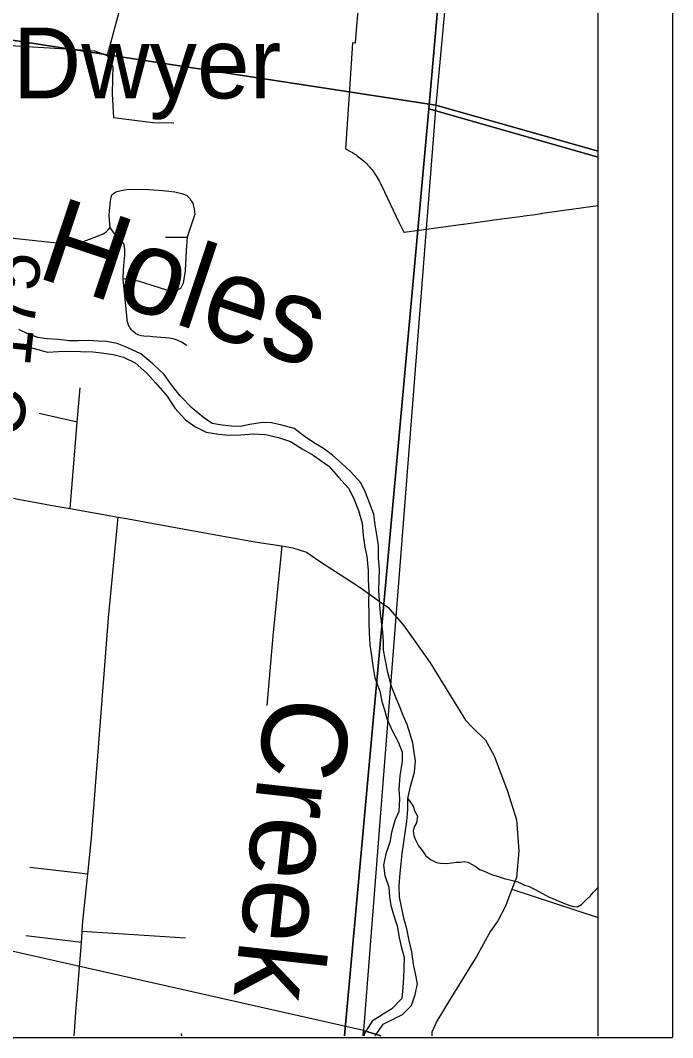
# Model space of a CAD drawing. Extents: x 0 to 34, y 0 to 22.
# Drawn here: x 8.273 to 9, y 14 to 15.134 of the extents above; entities that cross this region are included whole.
import ezdxf

# ---------------------------------------------------------------- set-up
doc = ezdxf.new("R2010")
doc.units = 0
for name, color, linetype in [('GM_X_County_Road', 7, 'Continuous'), ('GM_X_County_Road_Text', 7, 'Continuous'), ('GM_X_Interchange_Ramps', 7, 'Continuous'), ('GM_X_Interstate_Route', 7, 'Continuous'), ('GM_X_Minor_River', 7, 'Continuous'), ('GM_X_Minor_River_Text', 7, 'Continuous'), ('GM_X_Section', 7, 'Continuous'), ('GM_X_State_Shield', 7, 'Continuous'), ('GM_X_Township_Road', 7, 'Continuous'), ('GM_X_Unincorporated_Text', 7, 'Continuous'), ('SH_Data', 7, 'Continuous')]:
    doc.layers.add(name, color=color, linetype=linetype)

msp = doc.modelspace()

# ---------------------------------------------------------------- linework, layer by layer
at = {"layer": 'GM_X_County_Road'}
for points in [[(8.265, 14.6016), (8.2702, 14.6006), (8.3102, 14.5931), (8.328, 14.59), (8.3817, 14.5804), (8.3909, 14.5788)], [(8.3909, 14.5788), (8.4212, 14.5734), (8.4637, 14.5657)], [(8.4637, 14.5657), (8.5052, 14.5581), (8.5298, 14.5537), (8.5387, 14.5523), (8.5641, 14.5483), (8.5766, 14.5463), (8.5915, 14.5414), (8.6063, 14.5315), (8.6482, 14.5043), (8.6542, 14.5001)], [(8.6542, 14.5001), (8.678, 14.483), (8.6796, 14.4819)], [(8.6796, 14.4819), (8.6827, 14.4797), (8.7, 14.4599), (8.7296, 14.418), (8.7691, 14.3539), (8.7765, 14.3464), (8.7913, 14.3316), (8.8011, 14.3144), (8.8159, 14.2749), (8.8258, 14.2428), (8.8283, 14.2083), (8.8258, 14.1787), (8.8208, 14.1656), (8.8135, 14.1466), (8.8049, 14.1302), (8.797, 14.1187), (8.7811, 14.0904), (8.7518, 14.043), (8.737, 14.0183), (8.7315, 14.0062), (8.7313, 14.0019)]]:
    msp.add_lwpolyline(points, dxfattribs=at)
at = {"layer": 'GM_X_Interchange_Ramps'}
msp.add_lwpolyline([(8.6497, 15.1532), (8.6475, 15.1278), (8.646, 15.1095), (8.6459, 15.109), (8.643, 15.1092), (8.6396, 15.0577), (8.6352, 14.9911), (8.6383, 14.9895), (8.6399, 14.9887), (8.6415, 14.9878), (8.6428, 14.987), (8.6439, 14.9863), (8.6449, 14.9857), (8.6455, 14.9853), (8.6469, 14.9844), (8.6486, 14.9831), (8.6501, 14.982), (8.6517, 14.9808), (8.6531, 14.9796), (8.6548, 14.9781), (8.6566, 14.9765), (8.6585, 14.9747), (8.6598, 14.9734), (8.6607, 14.9723), (8.6611, 14.9719), (8.6622, 14.9707), (8.6632, 14.9695), (8.6645, 14.968), (8.6656, 14.9666), (8.667, 14.9645), (8.6684, 14.9626), (8.6695, 14.9609), (8.6706, 14.9591), (8.6717, 14.9573), (8.6726, 14.9555), (8.6734, 14.954), (8.6742, 14.9524), (8.6786, 14.9433), (8.6948, 14.9094), (8.7002, 14.8981), (8.7007, 14.8982), (8.728, 14.9019), (8.7659, 14.9071), (8.7665, 14.9072), (8.7672, 14.9072), (8.7694, 14.9075), (8.7989, 14.9116), (8.8004, 14.9118), (8.8329, 14.9162), (8.8344, 14.9164), (8.8465, 14.918), (8.8539, 14.9191), (8.8546, 14.9192), (8.9171, 14.9279), (8.9171, 17.2013)], dxfattribs=at)
at = {"layer": 'GM_X_Interstate_Route'}
for points in [[(8.745, 15.2262), (8.728, 15.0359), (8.9171, 14.9817), (8.9171, 17.2013)], [(8.634, 14.0019), (8.6778, 14.4836), (8.728, 15.0359), (8.745, 15.2262)], [(8.9171, 14.0019), (8.9171, 14.9817), (8.728, 15.0359), (8.6778, 14.4836), (8.634, 14.0019)]]:
    msp.add_lwpolyline(points, dxfattribs=at)
at = {"layer": 'GM_X_Minor_River'}
for points in [[(8.6683, 14.0019), (8.6771, 14.0152), (8.689, 14.021), (8.6989, 14.0258), (8.7086, 14.0359), (8.713, 14.0483), (8.7155, 14.0601), (8.7131, 14.0715), (8.711, 14.0818), (8.709, 14.0956), (8.7062, 14.1082), (8.7034, 14.1215), (8.7006, 14.1319), (8.6975, 14.146), (8.6954, 14.1567), (8.6949, 14.1692), (8.6963, 14.1833), (8.6973, 14.1943), (8.6983, 14.2053), (8.7, 14.2155), (8.7017, 14.2284), (8.7035, 14.241), (8.7045, 14.2546), (8.7048, 14.2668), (8.7077, 14.28), (8.7122, 14.2959), (8.7132, 14.3085), (8.7118, 14.318), (8.7101, 14.3283), (8.7073, 14.3386), (8.7041, 14.3493), (8.6994, 14.3593), (8.6958, 14.3689), (8.6918, 14.3785), (8.6863, 14.3915), (8.6825, 14.4072), (8.6794, 14.4225), (8.6776, 14.432), (8.6775, 14.4415), (8.6769, 14.4526), (8.6752, 14.4636), (8.6743, 14.4735), (8.673, 14.4876), (8.6725, 14.4987), (8.673, 14.5223), (8.6721, 14.5345), (8.672, 14.5485), (8.6703, 14.5585), (8.6682, 14.5718), (8.6666, 14.5836), (8.6619, 14.5963), (8.6576, 14.6078), (8.6521, 14.6185), (8.6409, 14.6313), (8.6309, 14.6402), (8.6208, 14.6496), (8.6107, 14.657), (8.6006, 14.6629), (8.5901, 14.67), (8.5778, 14.6793), (8.5642, 14.683), (8.5525, 14.6855), (8.5426, 14.6861), (8.5285, 14.6837), (8.5179, 14.6816), (8.508, 14.6818), (8.4978, 14.6828), (8.4864, 14.6849), (8.4767, 14.6915), (8.464, 14.7021), (8.4506, 14.7156), (8.441, 14.728), (8.4329, 14.7396), (8.4202, 14.7512), (8.4068, 14.7625), (8.3917, 14.7697), (8.3804, 14.7741), (8.3687, 14.7762), (8.3592, 14.7768), (8.3483, 14.7774), (8.3369, 14.7772), (8.327, 14.777), (8.3149, 14.7784), (8.3024, 14.7794), (8.2922, 14.7807), (8.2809, 14.7847), (8.2707, 14.7895)], [(8.2606, 14.7749), (8.2745, 14.7723), (8.2881, 14.7686), (8.3029, 14.7645), (8.315, 14.7651), (8.3275, 14.7656), (8.3397, 14.7653), (8.3533, 14.7647), (8.3632, 14.7637), (8.376, 14.7616), (8.3877, 14.7587), (8.4005, 14.7524), (8.4136, 14.7411), (8.4232, 14.7302), (8.4362, 14.7155), (8.445, 14.7021), (8.4569, 14.6889), (8.467, 14.6815), (8.4798, 14.6751), (8.4938, 14.673), (8.5048, 14.672), (8.5184, 14.6721), (8.5321, 14.6734), (8.5458, 14.6727), (8.5605, 14.6694), (8.5737, 14.6646), (8.5868, 14.6567), (8.5992, 14.6496), (8.6164, 14.6371), (8.6275, 14.6251), (8.6387, 14.6123), (8.6449, 14.6), (8.6496, 14.5878), (8.6539, 14.5736), (8.6547, 14.5599), (8.6567, 14.5469), (8.6588, 14.5366), (8.6604, 14.521), (8.6606, 14.5107), (8.6611, 14.4974), (8.6609, 14.486), (8.661, 14.473), (8.6612, 14.4631), (8.6617, 14.4513), (8.6622, 14.438), (8.6642, 14.4258), (8.6655, 14.4148), (8.6679, 14.4014), (8.6733, 14.3865), (8.6758, 14.375), (8.6786, 14.3654), (8.6811, 14.3559), (8.6869, 14.3432), (8.6939, 14.3298), (8.6982, 14.3183), (8.6984, 14.3084), (8.6958, 14.2921), (8.6947, 14.2769), (8.6953, 14.2662), (8.6946, 14.2522), (8.6902, 14.242), (8.6866, 14.2287), (8.6845, 14.2181), (8.68, 14.2049), (8.6775, 14.1924), (8.6792, 14.181), (8.6835, 14.1679), (8.6844, 14.1569), (8.6857, 14.1474), (8.6893, 14.1347), (8.6929, 14.1248), (8.6949, 14.1118), (8.6974, 14.1015), (8.7005, 14.0893), (8.7003, 14.0771), (8.6997, 14.0676), (8.6991, 14.0558), (8.6978, 14.0437), (8.6869, 14.0321), (8.6773, 14.0262), (8.665, 14.0184), (8.656, 14.0042), (8.656, 14.0019)], [(8.7048, 14.2668), (8.7111, 14.2574), (8.7118, 14.2537), (8.7155, 14.2471), (8.7145, 14.2395), (8.7117, 14.235), (8.7105, 14.2301), (8.7115, 14.2255), (8.7129, 14.2213), (8.7165, 14.214), (8.721, 14.2082), (8.7246, 14.2028), (8.7299, 14.1985), (8.7366, 14.1953), (8.7412, 14.1944), (8.7476, 14.1942), (8.7537, 14.1948), (8.7587, 14.1955), (8.7629, 14.1958), (8.7675, 14.1964), (8.7716, 14.1955), (8.7757, 14.1935), (8.7806, 14.1907), (8.7847, 14.1876), (8.7889, 14.186), (8.793, 14.184), (8.7979, 14.182), (8.8043, 14.1799), (8.8122, 14.1774), (8.8213, 14.1753), (8.8274, 14.1736), (8.8349, 14.17), (8.8394, 14.1688), (8.8465, 14.1652), (8.8623, 14.1568), (8.8665, 14.1552), (8.8732, 14.1523), (8.8777, 14.1503), (8.8853, 14.1475), (8.8894, 14.1462), (8.894, 14.1457), (8.8982, 14.1483), (8.9037, 14.1535), (8.908, 14.1579), (8.9115, 14.162), (8.9166, 14.1672), (8.9171, 14.1686)]]:
    msp.add_lwpolyline(points, dxfattribs=at)
at = {"layer": 'GM_X_Section'}
for points in [[(7.8045, 16.1663), (8.8322, 16.077), (8.7359, 15.0399), (7.7155, 15.1965)], [(7.7155, 15.1965), (8.7359, 15.0399), (8.6553, 14.0079), (7.6347, 14.2379)]]:
    msp.add_lwpolyline(points, close=True, dxfattribs=at)
at = {"layer": 'GM_X_State_Shield'}
msp.add_lwpolyline([(8.9171, 14.9885), (8.9171, 16.0539), (8.8322, 16.077), (8.7359, 15.0399)], close=True, dxfattribs=at)
for points in [[(8.9171, 14.0019), (8.9171, 14.9885), (8.7359, 15.0399), (8.6553, 14.0079), (8.6744, 14.0019)], [(8.6547, 14.0019), (8.6553, 14.0079), (7.6347, 14.2379), (7.6133, 14.0019)], [(8.6744, 14.0019), (8.6553, 14.0079), (8.6547, 14.0019)]]:
    msp.add_lwpolyline(points, dxfattribs=at)
at = {"layer": 'GM_X_Township_Road'}
for p, q in [((8.4345, 14.8927), (8.4586, 14.8927)), ((8.336, 14.6863), (8.2936, 14.696)), ((8.3478, 14.1822), (8.2832, 14.1898)), ((8.8208, 14.1656), (8.9171, 14.1338)), ((8.3406, 14.1061), (8.2787, 14.1135)), ((8.3416, 14.1187), (8.4569, 14.1113)), ((8.4526, 14.0019), (8.4521, 14.0048))]:
    msp.add_line(p, q, dxfattribs=at)
for points in [[(8.3834, 15.1477), (8.3695, 15.0951)], [(8.1826, 15.0878), (8.219, 15.0927), (8.2438, 15.1034), (8.2554, 15.1068), (8.336, 15.1019), (8.3554, 15.1005), (8.3695, 15.0951), (8.3758, 15.083), (8.3753, 15.0694), (8.3748, 15.0524), (8.3763, 15.0262), (8.4204, 15.0204), (8.4438, 15.0203)], [(8.4583, 14.7717), (8.4523, 14.7757), (8.4473, 14.7779), (8.4431, 14.7792), (8.4385, 14.78), (8.434, 14.7802), (8.42, 14.7816), (8.415, 14.7821), (8.4125, 14.782), (8.4102, 14.7821), (8.4078, 14.7825), (8.4045, 14.7835), (8.401, 14.7853), (8.398, 14.7877), (8.3966, 14.7893), (8.3957, 14.7903), (8.3945, 14.792), (8.3932, 14.7945), (8.3923, 14.797), (8.3918, 14.7992), (8.3918, 14.8012), (8.3872, 14.8461), (8.3874, 14.8563), (8.3884, 14.8653), (8.3889, 14.8726), (8.3889, 14.8791), (8.3878, 14.8855), (8.3854, 14.8885), (8.3776, 14.8964), (8.3728, 14.9034), (8.3719, 14.9118), (8.3717, 14.9166), (8.3719, 14.9219), (8.373, 14.9328), (8.3737, 14.9374), (8.3747, 14.9399), (8.3766, 14.9415), (8.3792, 14.9432), (8.385, 14.9448), (8.3912, 14.9459), (8.3948, 14.9463), (8.4158, 14.9456), (8.4315, 14.9447), (8.445, 14.9431), (8.4537, 14.9411), (8.4583, 14.939), (8.4602, 14.9372), (8.4615, 14.9356), (8.4632, 14.933), (8.4649, 14.9304), (8.4653, 14.9287), (8.4663, 14.9241), (8.467, 14.9182), (8.4586, 14.8927), (8.4576, 14.8777), (8.4564, 14.8551), (8.4542, 14.8413), (8.451, 14.8352), (8.4431, 14.8314), (8.4042, 14.8437), (8.3872, 14.8461)], [(8.1992, 14.8986), (8.327, 14.8849), (8.3293, 14.8849), (8.3314, 14.885), (8.3342, 14.8852), (8.345, 14.8887), (8.3624, 14.8951), (8.3649, 14.8965), (8.3682, 14.8987), (8.3705, 14.9009), (8.3728, 14.9034)], [(8.328, 14.59), (8.336, 14.6863), (8.3391, 14.7248)], [(8.3325, 14.0019), (8.3348, 14.033), (8.3406, 14.1061), (8.3416, 14.1187), (8.3424, 14.1298), (8.3478, 14.1822), (8.352, 14.2229), (8.3596, 14.3236), (8.371, 14.468), (8.3817, 14.5804)], [(8.5641, 14.5483), (8.5542, 14.4476), (8.5476, 14.3702)]]:
    msp.add_lwpolyline(points, dxfattribs=at)
at = {"layer": 'SH_Data'}
for p in [(9, 17.3211), (2, 14)]:
    msp.add_line(p, (9, 14), dxfattribs=at)

# ---------------------------------------------------------------- texts
at = {"layer": 'GM_X_County_Road_Text'}
msp.add_text('C-175', height=0.05682, rotation=84.0948, dxfattribs=at).set_placement((8.2749, 14.6673))
at = {"layer": 'GM_X_Minor_River_Text'}
for s, rotation, p in [('Holes', 341.4816, (8.2884, 14.8486)), ('Creek', 263.6614, (8.5476, 14.3834))]:
    msp.add_text(s, height=0.0947, rotation=rotation, dxfattribs=at).set_placement(p)
at = {"layer": 'GM_X_Unincorporated_Text'}
msp.add_text('Dwyer', height=0.07898, rotation=0, dxfattribs=at).set_placement((8.2642, 15.0474))

doc.saveas('drawing.dxf')
